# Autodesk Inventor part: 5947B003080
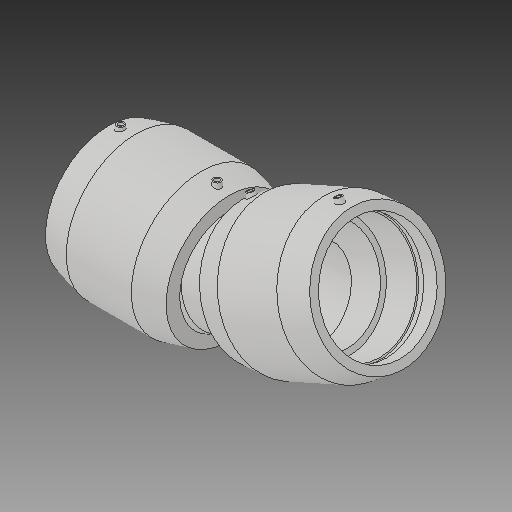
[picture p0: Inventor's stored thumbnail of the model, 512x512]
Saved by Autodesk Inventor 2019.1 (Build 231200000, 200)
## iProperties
Created: 2017-06
Part Number: 5947B003080
Material: Generic
Description: PLASSON ADJUSTABLE ELBOW ASTM 8''
Document SubType Name: Modeling
Designer: KIM
Mass: 16853.5 g
Surface Area: 12350.1 cm^2
Volume: 16853.5 cm^3
Density: 1 g/cm^3
Appearance: Default
Author: KIM
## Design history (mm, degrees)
derived "5947B.ipt"
feature "Solid1::5947B.ipt"
tag "TaggingFeature1"
body "Solid1"
other parameters: "d0" = 239.9792, "d2" = 278.892, "d3" = 110.49, "d4" = 55.245, "d5" = 251.0028, "d7" = 218.7, "d8" = 168 deg, "d10" = 44.196, "d11" = 14.732, "d29" = 139.954, "d30" = 15, "d31" = 95.99168, "d34" = 5 deg, "d41" = 4, "d42" = 14, "d43" = 0, "d48" = 196.83, "d49" = 24 deg, "d50" = 599.948, "d51" = 78 deg, "d52" = 90 deg, "d55" = 64.7446, "d57" = 168 deg, "d58" = 12.94892, "d60" = 73.76227, "d62" = 3, "d63" = 0, "d_" = 218.7, "L_" = 599.948, "L_1" = 110.49, "D_" = 278.892, "A_" = 139.954, "d54" = 129.4892, "d59" = 245.87423
